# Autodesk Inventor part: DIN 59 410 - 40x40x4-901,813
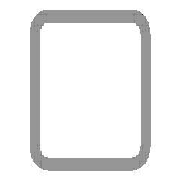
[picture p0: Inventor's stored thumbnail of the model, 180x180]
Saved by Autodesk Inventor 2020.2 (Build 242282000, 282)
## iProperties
Manager: www.cadconsulting.pl
Company: Fabian Stasiak CAD Consulting
IsCustomPart: 1
_CCFamilyMember: 20
_CCFamilyDisplayName: DIN 59410 (Kwadrat) - Rurki stalowe o przekroju kwadratowym formowane na gorąco
_FrameMemberDoc: Frame Member File
_Version: 15.0.0
_GetPNFromCC: 1
Created: 2015-01
Part Number: DIN 59 410 - 40x40x4-901,813
Material: Stal, miękka
Description: Rurki stalowe o przekroju kwadratowym formowane na gorąco
Document SubType Name: Modellieren
Standard: DIN
Designer: F.Stasiak
Standards Organization: DIN
Language: pl-PL
Size Designation: 40x40x4
Categories: <MemberInstance><Categories><Category DisplayName="Kształtowniki konstrukcyjne" InternalName="089c4875-fa83-4c05-b084-43b9cc11f5ed" Mnemonic="GRDR"><CategoryPar
Stock Number: 40x40x4
Density: 7.85 g/cm^3
Appearance: Częściowo polerowana
Mass: 3599.13 g
Surface Area: 2308.84 cm^2
Volume: 458.488 cm^3
Catalog Web Link: www.expertbooks.pl
G_W: 40,000 mm
G_H: 40,000 mm
+B8222331-784B-4EA2-A025-7E93C749D730+CUTDETAIL1: Wytnij
+8525DED3-63AA-4109-9360-F22161789C46+CUTDETAIL2: Wytnij
G_L: 901,813 mm
Author: F.Stasiak
Subject: Zbiór ćwiczeń. Autodesk Inventor 2020. Kurs Professional
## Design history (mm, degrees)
node "Płaszczyzna początkowa"
node "Płaszczyzna końcowa"
sketch "Szkic1"
  geometry: L1 (-12, 20)-(12, 20); L2 (20, 12)-(20, -12); L3 (12, -20)-(-12, -20); L4 (-20, -12)-(-20, 12); L5 (-30.32, 0)-(30.32, 0) reference; L6 (0, -30.32)-(0, 30.32) reference; L7 (-12, 16)-(12, 16); L8 (16, 12)-(16, -12); L9 (12, -16)-(-12, -16); L10 (-16, -12)-(-16, 12); A1 r 8 centre (-12, 12) between (-12, 20) and (-20, 12); A2 r 8 centre (12, 12) between (20, 12) and (12, 20); A3 r 8 centre (12, -12) between (12, -20) and (20, -12); A4 r 8 centre (-12, -12) between (-20, -12) and (-12, -20); A5 r 4 centre (-12, 12) between (-12, 16) and (-16, 12); A6 r 4 centre (12, 12) between (16, 12) and (12, 16); A7 r 4 centre (12, -12) between (12, -16) and (16, -12); A8 r 4 centre (-12, -12) between (-16, -12) and (-12, -16); 3 further points
  constraints: 16 end point, 16 point on circle, 8 centre point, 8 tangent, 6 point on line, 4 parallel, 3 equal radius, 3 perpendicular, 1 horizontal, 7 other
  dimensions: "b" = 40 distance of point (-20, 20) point (20, 20); "msp_r" = 8 radius of A1 (= 2 x ParT); "d8" = 20 distance between parallel lines of L4 L6 (= d9); "d9" = 20 distance between parallel lines of L3 L5 (= 0.5 x b); "d10" = 4 distance between parallel lines of L3 L9 (= ParT)
extrude "Bryła" new body sketch "Szkic1" taper "d4" = 0 deg; stored distance "NLG" = 10
node "Driven Length"
  sketch "Sketch2"
    geometry: L1 (0, 0)-(10, 0) reference
    constraints: 2 end point, 1 horizontal
  workplane "Work Plane3"
  sketch "Sketch3"
    geometry: L1 (-2, 16.981)-(12, 16.981) reference; L2 (-2, 918.794)-(12, 918.794) reference
    dimensions: "d14" = 901.81304 distance between parallel lines of L1 L2 (derived)
node "Płaszczyzna konstrukcyjna4"
feature "Podział1"
node "Płaszczyzna konstrukcyjna5"
feature "Podział2"
body "Solid1"
other parameters: "ParT" = 4, "G_OFFSET_START" = -16.98119 [user parameter; used in 1 equation term], "G_OFFSET_END" = -24.60389 [user parameter; used in 1 equation term], "d11" = 16.98119 (= -G_OFFSET_START), "d12" = 918.79423 (= G_OFFSET_END + B_L), "G_L" = 901.81304 (= d14) [user parameter], "B_L" = 943.39811 [user parameter; used in 1 equation term], "d13" = 90 deg
